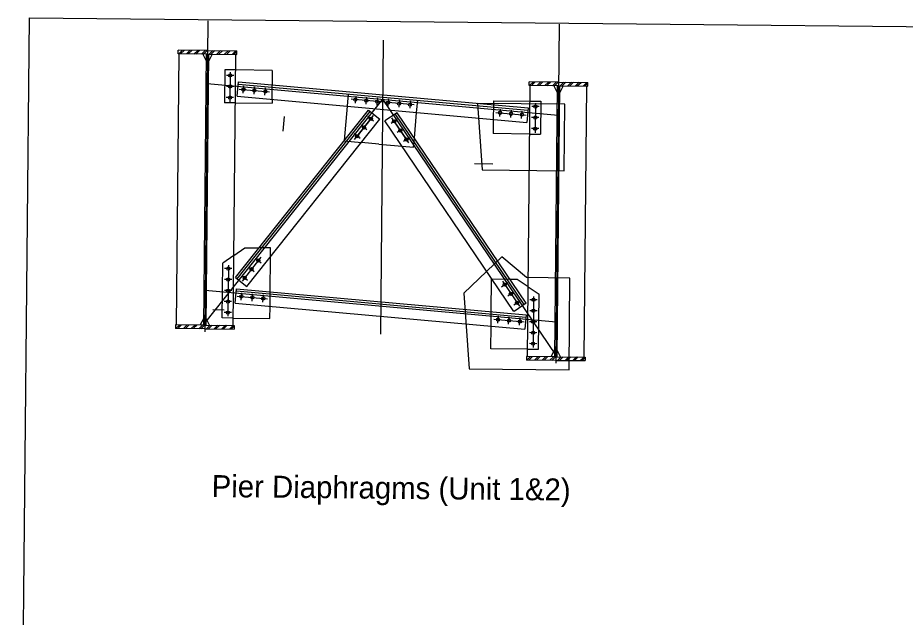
# Model space of a CAD drawing. Extents: x 632047 to 632524, y 378162 to 378491.
# Drawn here: x 632199.99 to 632220.21, y 378389.8 to 378403.44 of the extents above; entities that cross this region are included whole.
import ezdxf

# ---------------------------------------------------------------- set-up
doc = ezdxf.new("R2010")
doc.units = 0
for name, color, linetype in [('BD-EXIST-COSS', 7, 'Continuous'), ('BD-EXIST-OSB', 7, 'Continuous'), ('BD-LEGEND', 7, 'Continuous'), ('BD-PROP-COSS', 7, 'Continuous'), ('BD-PROP-OSB', 7, 'Continuous')]:
    doc.layers.add(name, color=color, linetype=linetype)

msp = doc.modelspace()

# ---------------------------------------------------------------- linework, layer by layer
at = {"layer": 'BD-EXIST-OSB'}
for p, q in [((632203.649, 378402.62), (632203.65, 378402.703)), ((632204.316, 378402.697), (632203.65, 378402.703)), ((632204.316, 378402.697), (632204.983, 378402.69)), ((632204.982, 378402.607), (632204.983, 378402.69)), ((632203.608, 378396.453), (632203.67, 378402.62)), ((632204.315, 378402.613), (632203.649, 378402.62)), ((632204.211, 378402.614), (632204.293, 378402.447)), ((632204.233, 378396.447), (632204.295, 378402.614)), ((632204.336, 378402.613), (632204.275, 378396.447)), ((632204.315, 378402.613), (632204.982, 378402.607)), ((632204.42, 378402.612), (632204.335, 378402.446)), ((632204.9, 378396.441), (632204.961, 378402.607)), ((632204.708, 378402.255), (632204.7, 378401.505)), ((632204.958, 378402.253), (632204.708, 378402.255)), ((632205.791, 378402.244), (632204.958, 378402.253)), ((632205.791, 378402.244), (632205.788, 378401.917)), ((632204.993, 378401.654), (632205.023, 378401.986)), ((632205.019, 378401.934), (632211.611, 378401.338)), ((632205.023, 378401.986), (632211.616, 378401.39)), ((632205.784, 378401.582), (632205.788, 378401.917)), ((632211.602, 378395.734), (632211.663, 378401.9)), ((632211.642, 378401.9), (632211.643, 378401.984)), ((632212.309, 378401.894), (632211.642, 378401.9)), ((632212.31, 378401.977), (632211.643, 378401.984)), ((632212.205, 378401.895), (632212.286, 378401.727)), ((632212.227, 378395.728), (632212.288, 378401.894)), ((632212.33, 378401.894), (632212.268, 378395.727)), ((632212.309, 378401.894), (632212.975, 378401.887)), ((632212.31, 378401.977), (632212.976, 378401.971)), ((632212.413, 378401.893), (632212.328, 378401.727)), ((632212.893, 378395.721), (632212.954, 378401.887)), ((632212.975, 378401.887), (632212.976, 378401.971)), ((632204.993, 378401.654), (632211.586, 378401.058)), ((632207.501, 378401.427), (632207.527, 378401.707)), ((632204.95, 378401.503), (632204.7, 378401.505)), ((632204.95, 378401.503), (632205.784, 378401.495)), ((632205.784, 378401.582), (632205.784, 378401.495)), ((632209.078, 378401.284), (632209.104, 378401.565)), ((632210.825, 378401.461), (632210.822, 378401.127)), ((632210.826, 378401.554), (632210.825, 378401.461)), ((632210.826, 378401.554), (632211.659, 378401.546)), ((632211.659, 378401.546), (632211.909, 378401.544)), ((632211.909, 378401.544), (632211.902, 378400.794)), ((632204.952, 378397.53), (632207.981, 378401.342)), ((632204.993, 378397.498), (632208.022, 378401.309)), ((632207.431, 378400.65), (632207.501, 378401.427)), ((632207.981, 378401.342), (632208.242, 378401.134)), ((632208.632, 378401.281), (632208.356, 378401.094)), ((632211.527, 378396.917), (632208.589, 378401.252)), ((632211.57, 378396.946), (632208.632, 378401.281)), ((632209.026, 378400.7), (632209.078, 378401.284)), ((632211.616, 378401.39), (632211.586, 378401.058)), ((632205.213, 378397.323), (632208.242, 378401.134)), ((632211.294, 378396.759), (632208.356, 378401.094)), ((632210.822, 378401.127), (632210.819, 378400.804)), ((632207.431, 378400.65), (632207.43, 378400.639)), ((632207.43, 378400.639), (632207.82, 378400.603)), ((632209.008, 378400.497), (632209.026, 378400.7)), ((632211.652, 378400.796), (632210.819, 378400.804)), ((632211.652, 378400.796), (632211.902, 378400.794)), ((632208.219, 378400.568), (632207.82, 378400.603)), ((632208.219, 378400.568), (632208.745, 378400.52)), ((632208.745, 378400.52), (632209.008, 378400.497)), ((632204.916, 378398.034), (632205.168, 378398.209)), ((632205.168, 378398.209), (632205.489, 378398.206)), ((632205.751, 378398.203), (632205.489, 378398.206)), ((632205.749, 378397.997), (632205.751, 378398.203)), ((632204.916, 378398.034), (632204.664, 378397.86)), ((632204.652, 378396.61), (632204.664, 378397.86)), ((632205.741, 378397.208), (632205.749, 378397.997)), ((632204.952, 378397.53), (632205.213, 378397.323)), ((632210.778, 378396.754), (632210.786, 378397.492)), ((632210.797, 378397.492), (632210.786, 378397.492)), ((632211.203, 378397.488), (632210.797, 378397.492)), ((632211.369, 378397.486), (632211.203, 378397.488)), ((632211.617, 378397.317), (632211.369, 378397.486)), ((632204.947, 378396.944), (632204.977, 378397.276)), ((632204.972, 378397.225), (632211.565, 378396.631)), ((632204.977, 378397.276), (632211.569, 378396.683)), ((632205.738, 378396.873), (632205.741, 378397.208)), ((632211.617, 378397.317), (632211.866, 378397.148)), ((632211.853, 378395.898), (632211.866, 378397.148)), ((632204.947, 378396.944), (632211.539, 378396.351)), ((632205.735, 378396.599), (632205.738, 378396.873)), ((632211.572, 378396.943), (632211.296, 378396.756)), ((632204.15, 378396.448), (632204.235, 378396.614)), ((632204.358, 378396.446), (632204.277, 378396.613)), ((632204.902, 378396.607), (632204.652, 378396.61)), ((632204.902, 378396.607), (632205.735, 378396.599)), ((632210.775, 378396.42), (632210.778, 378396.754)), ((632211.569, 378396.683), (632211.539, 378396.351)), ((632203.588, 378396.454), (632203.587, 378396.37)), ((632204.254, 378396.447), (632203.588, 378396.454)), ((632204.254, 378396.447), (632204.921, 378396.44)), ((632204.921, 378396.44), (632204.92, 378396.357)), ((632210.77, 378395.909), (632210.775, 378396.42)), ((632204.253, 378396.364), (632203.587, 378396.37)), ((632204.253, 378396.364), (632204.92, 378396.357)), ((632211.603, 378395.901), (632210.77, 378395.909)), ((632211.603, 378395.901), (632211.853, 378395.898)), ((632212.143, 378395.729), (632212.228, 378395.894)), ((632212.352, 378395.726), (632212.27, 378395.894)), ((632211.581, 378395.734), (632211.58, 378395.651)), ((632212.247, 378395.644), (632211.58, 378395.651)), ((632212.247, 378395.727), (632211.581, 378395.734)), ((632212.247, 378395.727), (632212.914, 378395.721)), ((632212.247, 378395.644), (632212.913, 378395.638)), ((632212.914, 378395.721), (632212.913, 378395.638))]:
    msp.add_line(p, q, dxfattribs=at)
for centre in [(632204.831, 378402.129), (632204.829, 378401.879), (632205.133, 378401.808), (632204.826, 378401.625), (632205.382, 378401.786), (632205.631, 378401.763), (632207.682, 378401.578), (632207.931, 378401.555), (632208.18, 378401.533), (632208.429, 378401.51), (632208.678, 378401.488), (632208.927, 378401.465), (632211.783, 378401.42), (632210.979, 378401.28), (632211.228, 378401.257), (632211.477, 378401.235), (632208.034, 378401.14), (632208.564, 378401.084), (632211.781, 378401.17), (632207.878, 378400.945), (632208.705, 378400.877), (632211.778, 378400.916), (632207.723, 378400.749), (632208.845, 378400.67), (632205.472, 378397.916), (632204.788, 378397.733), (632205.316, 378397.72), (632204.785, 378397.483), (632205.161, 378397.525), (632211.083, 378397.367), (632204.783, 378397.23), (632211.224, 378397.16), (632204.78, 378396.983), (632205.086, 378397.099), (632205.335, 378397.077), (632205.584, 378397.054), (632211.364, 378396.953), (632211.739, 378397.024), (632211.737, 378396.774), (632204.778, 378396.733), (632210.932, 378396.573), (632211.181, 378396.551), (632211.43, 378396.528), (632211.734, 378396.521), (632211.732, 378396.274), (632211.729, 378396.024)]:
    msp.add_circle(centre, 0.0365, dxfattribs=at)
at = {"layer": 'BD-LEGEND'}
for p, q in [((632203.659, 378402.62), (632203.743, 378402.702)), ((632203.703, 378402.619), (632203.787, 378402.702)), ((632203.833, 378402.618), (632203.917, 378402.701)), ((632203.876, 378402.618), (632203.96, 378402.7)), ((632204.006, 378402.616), (632204.091, 378402.699)), ((632204.05, 378402.616), (632204.106, 378402.671)), ((632204.106, 378402.671), (632204.134, 378402.698)), ((632204.18, 378402.615), (632204.264, 378402.697)), ((632204.223, 378402.614), (632204.308, 378402.697)), ((632204.354, 378402.613), (632204.438, 378402.695)), ((632204.397, 378402.613), (632204.481, 378402.695)), ((632204.527, 378402.611), (632204.611, 378402.694)), ((632204.571, 378402.611), (632204.655, 378402.693)), ((632204.701, 378402.61), (632204.785, 378402.692)), ((632204.744, 378402.609), (632204.828, 378402.692)), ((632204.874, 378402.608), (632204.959, 378402.69)), ((632204.918, 378402.607), (632204.983, 378402.671)), ((632211.652, 378401.9), (632211.737, 378401.983)), ((632211.696, 378401.9), (632211.78, 378401.982)), ((632211.826, 378401.899), (632211.91, 378401.981)), ((632211.869, 378401.898), (632211.954, 378401.981)), ((632212, 378401.897), (632212.084, 378401.979)), ((632212.043, 378401.896), (632212.099, 378401.952)), ((632212.099, 378401.952), (632212.127, 378401.979)), ((632212.173, 378401.895), (632212.257, 378401.978)), ((632212.217, 378401.895), (632212.301, 378401.977)), ((632212.347, 378401.893), (632212.431, 378401.976)), ((632212.39, 378401.893), (632212.474, 378401.976)), ((632212.52, 378401.892), (632212.605, 378401.974)), ((632212.564, 378401.891), (632212.648, 378401.974)), ((632212.694, 378401.89), (632212.778, 378401.973)), ((632212.737, 378401.89), (632212.822, 378401.972)), ((632212.868, 378401.888), (632212.952, 378401.971)), ((632212.911, 378401.888), (632212.976, 378401.952)), ((632203.597, 378396.37), (632203.681, 378396.453)), ((632203.64, 378396.37), (632203.725, 378396.452)), ((632203.771, 378396.368), (632203.855, 378396.451)), ((632203.814, 378396.368), (632203.898, 378396.451)), ((632203.944, 378396.367), (632204.028, 378396.449)), ((632203.988, 378396.366), (632204.044, 378396.421)), ((632204.044, 378396.421), (632204.072, 378396.449)), ((632204.118, 378396.365), (632204.202, 378396.448)), ((632204.161, 378396.365), (632204.245, 378396.447)), ((632204.291, 378396.363), (632204.376, 378396.446)), ((632204.335, 378396.363), (632204.419, 378396.445)), ((632204.465, 378396.362), (632204.549, 378396.444)), ((632204.508, 378396.361), (632204.593, 378396.444)), ((632204.639, 378396.36), (632204.723, 378396.442)), ((632204.682, 378396.359), (632204.766, 378396.442)), ((632204.812, 378396.358), (632204.896, 378396.441)), ((632204.856, 378396.358), (632204.921, 378396.421)), ((632211.59, 378395.651), (632211.674, 378395.733)), ((632211.634, 378395.65), (632211.718, 378395.733)), ((632211.764, 378395.649), (632211.848, 378395.731)), ((632211.807, 378395.649), (632211.891, 378395.731)), ((632211.937, 378395.647), (632212.022, 378395.73)), ((632211.981, 378395.647), (632212.037, 378395.702)), ((632212.037, 378395.702), (632212.065, 378395.729)), ((632212.111, 378395.646), (632212.195, 378395.728)), ((632212.154, 378395.645), (632212.239, 378395.728)), ((632212.285, 378395.644), (632212.369, 378395.726)), ((632212.328, 378395.643), (632212.412, 378395.726)), ((632212.458, 378395.642), (632212.542, 378395.725)), ((632212.502, 378395.642), (632212.586, 378395.724)), ((632212.632, 378395.64), (632212.716, 378395.723)), ((632212.675, 378395.64), (632212.759, 378395.722)), ((632212.805, 378395.639), (632212.89, 378395.721)), ((632212.849, 378395.638), (632212.914, 378395.702))]:
    msp.add_line(p, q, dxfattribs=at)
at = {"layer": 'BD-PROP-COSS'}
for p, q in [((632210.464, 378401.492), (632210.571, 378399.98)), ((632212.45, 378401.473), (632210.464, 378401.492)), ((632212.435, 378399.961), (632212.45, 378401.473)), ((632206.063, 378401.196), (632206.033, 378400.864)), ((632210.812, 378400.11), (632210.398, 378400.114)), ((632210.567, 378399.98), (632212.435, 378399.961)), ((632211.016, 378398), (632210.15, 378397.173)), ((632211.578, 378397.531), (632211.016, 378398)), ((632212.565, 378397.519), (632211.578, 378397.531)), ((632212.549, 378395.429), (632212.565, 378397.519)), ((632210.15, 378397.173), (632210.271, 378395.452)), ((632204.695, 378396.789), (632204.436, 378396.792)), ((632210.271, 378395.452), (632212.549, 378395.429))]:
    msp.add_line(p, q, dxfattribs=at)
msp.add_lwpolyline([(632200.26, 378403.442), (632235.587, 378403.091), (632235.319, 378376.155), (632199.993, 378376.506)], close=True, dxfattribs=at)
at = {"layer": 'BD-PROP-OSB'}
for p, q in [((632204.323, 378403.375), (632204.253, 378396.292)), ((632212.323, 378403.295), (632212.246, 378395.584)), ((632208.319, 378402.935), (632208.252, 378396.24)), ((632204.915, 378402.128), (632204.748, 378402.13)), ((632204.832, 378402.205), (632204.826, 378401.531)), ((632204.309, 378401.947), (632212.302, 378401.227)), ((632204.912, 378401.878), (632204.746, 378401.88)), ((632205.125, 378401.725), (632205.14, 378401.891)), ((632205.374, 378401.703), (632205.389, 378401.869)), ((632205.376, 378401.703), (632205.388, 378401.869)), ((632205.623, 378401.68), (632205.638, 378401.846)), ((632205.039, 378401.817), (632205.725, 378401.755)), ((632207.69, 378401.661), (632207.675, 378401.495)), ((632207.939, 378401.638), (632207.924, 378401.472)), ((632204.255, 378396.489), (632208.305, 378401.587)), ((632204.91, 378401.628), (632204.743, 378401.63)), ((632209.022, 378401.457), (632207.588, 378401.586)), ((632208.188, 378401.616), (632208.173, 378401.45)), ((632212.248, 378395.769), (632208.305, 378401.587)), ((632208.437, 378401.593), (632208.422, 378401.427)), ((632208.686, 378401.571), (632208.671, 378401.405)), ((632208.935, 378401.548), (632208.92, 378401.382)), ((632211.784, 378401.496), (632211.777, 378400.822)), ((632210.884, 378401.288), (632211.571, 378401.227)), ((632210.971, 378401.197), (632210.986, 378401.363)), ((632211.22, 378401.174), (632211.235, 378401.34)), ((632211.469, 378401.152), (632211.484, 378401.318)), ((632211.866, 378401.419), (632211.7, 378401.421)), ((632207.664, 378400.675), (632208.092, 378401.214)), ((632208.034, 378401.14), (632207.723, 378400.749)), ((632208.099, 378401.088), (632207.968, 378401.192)), ((632208.633, 378401.131), (632208.495, 378401.038)), ((632208.898, 378400.592), (632208.511, 378401.163)), ((632208.564, 378401.084), (632208.845, 378400.67)), ((632211.864, 378401.169), (632211.697, 378401.171)), ((632207.943, 378400.893), (632207.813, 378400.996)), ((632208.774, 378400.924), (632208.636, 378400.831)), ((632211.861, 378400.919), (632211.695, 378400.921)), ((632207.788, 378400.697), (632207.657, 378400.801)), ((632208.914, 378400.717), (632208.776, 378400.624)), ((632204.789, 378397.809), (632204.777, 378396.65)), ((632205.531, 378397.99), (632205.102, 378397.45)), ((632205.407, 378397.968), (632205.537, 378397.864)), ((632204.871, 378397.733), (632204.704, 378397.734)), ((632205.251, 378397.772), (632205.381, 378397.669)), ((632204.869, 378397.483), (632204.702, 378397.484)), ((632205.095, 378397.576), (632205.226, 378397.473)), ((632211.014, 378397.32), (632211.152, 378397.414)), ((632211.03, 378397.445), (632211.417, 378396.875)), ((632204.259, 378397.239), (632212.255, 378396.519)), ((632204.866, 378397.233), (632204.699, 378397.234)), ((632211.155, 378397.113), (632211.293, 378397.207)), ((632204.992, 378397.108), (632205.678, 378397.046)), ((632205.079, 378397.016), (632205.094, 378397.182)), ((632205.328, 378396.994), (632205.343, 378397.16)), ((632205.577, 378396.971), (632205.592, 378397.137)), ((632211.295, 378396.906), (632211.433, 378397)), ((632211.823, 378397.023), (632211.656, 378397.025)), ((632211.74, 378397.1), (632211.729, 378395.941)), ((632204.864, 378396.983), (632204.697, 378396.984)), ((632204.861, 378396.733), (632204.695, 378396.734)), ((632210.924, 378396.49), (632210.939, 378396.656)), ((632211.173, 378396.468), (632211.188, 378396.634)), ((632211.422, 378396.445), (632211.437, 378396.611)), ((632211.82, 378396.773), (632211.654, 378396.775)), ((632210.838, 378396.581), (632211.524, 378396.52)), ((632211.818, 378396.523), (632211.651, 378396.525)), ((632211.815, 378396.273), (632211.649, 378396.275)), ((632211.813, 378396.023), (632211.646, 378396.025))]:
    msp.add_line(p, q, dxfattribs=at)

# ---------------------------------------------------------------- texts
at = {"layer": 'BD-EXIST-COSS'}
msp.add_text('Pier Diaphragms (Unit 1&2)', height=0.5, rotation=359.4304, dxfattribs=at).set_placement((632204.408, 378392.534))

doc.saveas('drawing.dxf')
